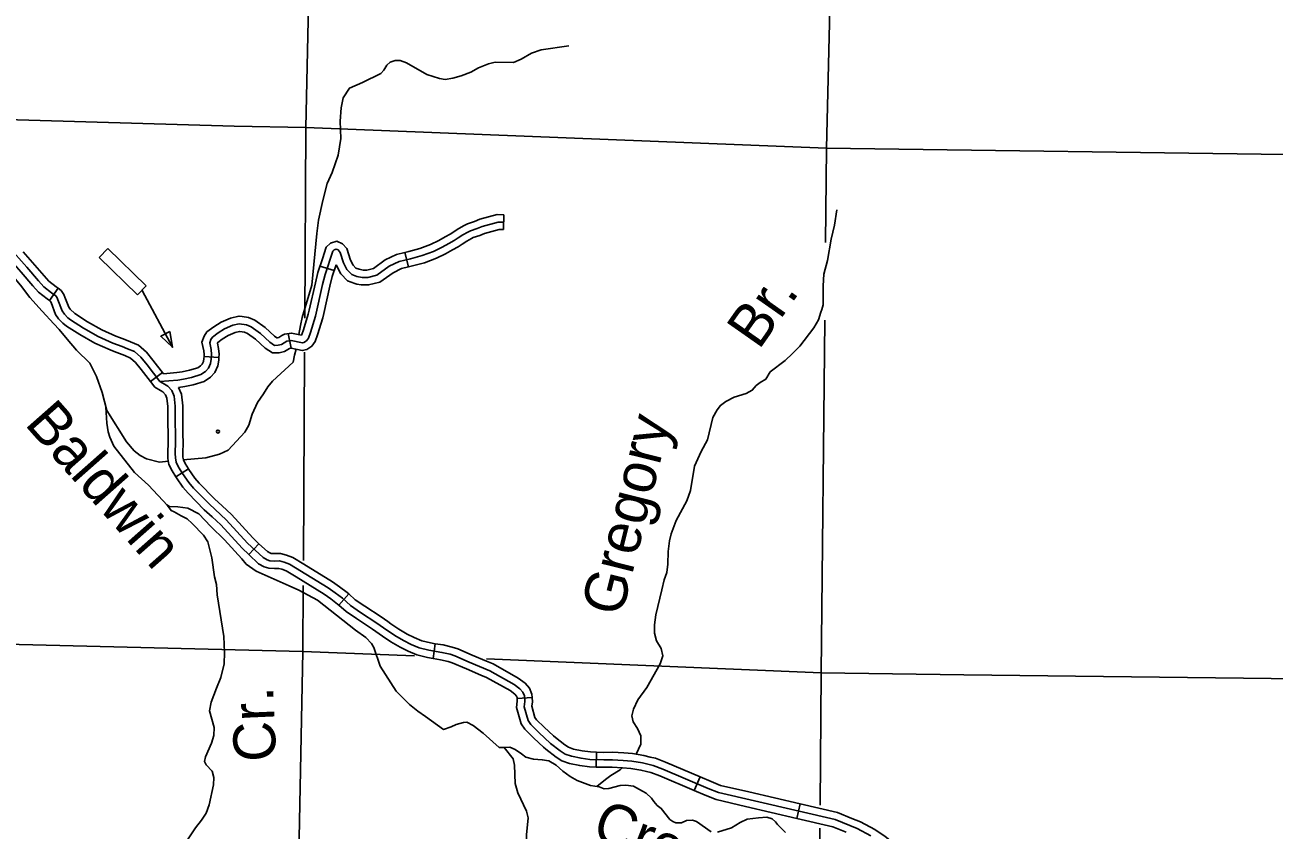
# Model space of a CAD drawing. Extents: x 0 to 3171, y 0 to 2059.
# Drawn here: x 1663.2 to 1872.3, y 380.6 to 515.4 of the extents above; entities that cross this region are included whole.
import ezdxf

# ---------------------------------------------------------------- set-up
doc = ezdxf.new("R2010")
doc.units = 0
for name, color, linetype in [('Level 35', 7, 'Continuous'), ('Level 45', 7, 'Continuous'), ('Level 5', 7, 'Continuous'), ('Level 57', 7, 'Continuous')]:
    doc.layers.add(name, color=color, linetype=linetype)

msp = doc.modelspace()

# ---------------------------------------------------------------- linework, layer by layer
at = {"layer": 'Level 35'}
for points in [[(1754.23, 511.88), (1749.65, 511.2), (1748, 510.68), (1746.26, 509.67), (1744.97, 509.12), (1741.93, 509.17), (1740.82, 508.89), (1739.11, 508.21), (1737.83, 507.46), (1736.21, 506.86), (1734.82, 506.48), (1733.55, 506.25), (1732.6, 506.41), (1730.47, 507.11), (1727.08, 509.02), (1726.03, 509.43), (1725.21, 509.44), (1724.35, 509.16), (1723.78, 508.64), (1723.3, 507.82), (1722.79, 507.24), (1719.74, 505.73), (1717.54, 504.82), (1716.46, 503.16), (1716.13, 501.49), (1715.97, 499.27), (1716.08, 496.34), (1715.63, 493.59), (1714.62, 490.66), (1713.81, 488.85), (1713.07, 485.96), (1712.36, 482.7), (1712.07, 480.48), (1711.26, 471.82)], [(1799.08, 484.44), (1798.69, 481.85), (1798.17, 479.51), (1797.54, 475.95), (1796.92, 473.65), (1796.79, 471.71), (1796.82, 468.5), (1796.62, 467.7), (1796.42, 467.26)], [(1626.29, 482.56), (1629.16, 480.94), (1631.33, 479.93), (1633.71, 479.38), (1637.13, 479.58), (1650.46, 481.71), (1651.54, 481.66), (1654.1, 481.22), (1656.23, 479.5), (1658.01, 477.4), (1659.51, 475.35), (1661.02, 473.52), (1662.47, 471.81), (1664.02, 469.74), (1666.13, 467.43), (1668.06, 465.34)], [(1709.06, 463.54), (1709.32, 465.03), (1709.65, 466.38), (1711.26, 471.82)], [(1796.42, 467.26), (1796.02, 465.99), (1795.27, 464.64), (1792.9, 461.6), (1791.7, 460.36), (1790.44, 459.2), (1787.97, 457.26), (1787.25, 456.06), (1786.29, 455.49), (1785.62, 454.98), (1784.94, 454.2), (1783.92, 453.67), (1781.92, 453.06), (1780.54, 452.32), (1779.61, 451.65), (1779.07, 450.91), (1778.37, 449.63), (1777.45, 445.89), (1776.42, 443.94), (1775.29, 441.5), (1774.64, 437.43), (1773.99, 435.7), (1772.23, 432.38), (1771.38, 430.17), (1771.09, 428.96), (1770.85, 427.21), (1770.8, 425.07), (1770.67, 423.69), (1770.22, 422.46), (1769.8, 420.8), (1768.84, 416.57), (1768.57, 414.93), (1768.57, 413.51), (1768.92, 412.25), (1769.68, 410.95), (1769.97, 409.72), (1769.55, 408.36), (1767.28, 404.42), (1765.8, 402.33), (1765.06, 400.8), (1764.8, 399.66), (1765.02, 398.66), (1765.76, 397.53), (1766.29, 396.35), (1766.31, 394.95), (1765.53, 393.25)], [(1668.06, 465.34), (1668.93, 464.38), (1670.28, 462.75), (1671.84, 460.92), (1674.06, 458.74), (1675.23, 456.48), (1676.13, 453.82), (1676.94, 450.83), (1680.22, 445.56), (1681.52, 444.08), (1682.5, 443.27), (1683.58, 442.69), (1685.75, 442.18), (1687.23, 442.31)], [(1689.73, 442.54), (1693.49, 442.89), (1695.77, 443.48), (1697.24, 444.19), (1700.02, 447.21), (1700.71, 448.36), (1701.25, 450.17), (1702.13, 452.13), (1703.18, 453.6), (1703.9, 454.78), (1704.65, 455.73), (1708.09, 458.93), (1708.34, 460.08), (1708.63, 461.07)], [(1676.79, 451.39), (1676.93, 448.68), (1677.18, 447.22), (1677.41, 446.36), (1678.12, 444.82), (1681.56, 440.42), (1683.93, 438.28), (1687.07, 434.92), (1687.68, 434.08), (1688.19, 433.86), (1689.38, 433.15), (1690.35, 432.67), (1691.21, 431.91), (1693.1, 429.92), (1693.83, 428.83), (1694.5, 426.14), (1694.96, 422.97), (1695.3, 421.67), (1695.39, 419.96), (1696.5, 412.96), (1696.62, 410.31), (1696.56, 408.39), (1696.02, 406.08), (1695.26, 404.3), (1694.41, 401.99), (1694.11, 400.5), (1694.91, 397.75), (1694.85, 396.4), (1694.46, 395.12), (1693.45, 392.79), (1693.28, 392.02), (1693.54, 391.45), (1694.57, 390.39), (1694.86, 389.35), (1694.78, 388.11), (1694.04, 384.78), (1693.53, 383.37), (1692.79, 382.19), (1691.77, 380.91), (1689.45, 377.43)], [(1687, 434.99), (1687.44, 434.73), (1688.83, 434.7), (1690.5, 434.48), (1692.34, 433.53), (1694.34, 431.38), (1696.65, 429.17), (1699.5, 425.99), (1700.27, 425.09), (1701.94, 423.9), (1707.43, 421.45), (1709.04, 420.72), (1712.19, 419.03), (1718.54, 414.04), (1720.29, 412.8), (1721.24, 411.79), (1721.6, 411.12), (1722.7, 408.01), (1725.37, 403.8), (1727.61, 401.59), (1728.96, 400.44), (1730.25, 399.55), (1733.3, 397.4), (1734.54, 397.82), (1735.42, 398.24), (1736.63, 398.56), (1737.18, 398.59), (1738.22, 398.07), (1739.91, 396.76), (1742.6, 394.35), (1743.41, 394.35), (1744.4, 394.42), (1745.25, 394.04), (1746.35, 393.29), (1747.05, 392.73), (1748.33, 392.44), (1749.8, 392.33), (1750.92, 392.12), (1752.13, 391.41), (1753.27, 390.41), (1754.45, 389.5), (1755.66, 388.82), (1757.89, 388), (1759.32, 387.76), (1760.16, 387.46), (1760.94, 387.48), (1762.85, 388.02), (1763.81, 388.07), (1765.07, 387.89), (1766.57, 387.08), (1767.2, 386.7), (1768.07, 385.89), (1768.47, 385.33), (1769.03, 384.66), (1769.71, 384.16), (1771.16, 382.31), (1771.65, 381.97), (1772.16, 381.74), (1773.1, 381.77), (1773.95, 382.17), (1774.96, 382.23), (1775.61, 381.96), (1778.06, 380.27)], [(1743.41, 394.35), (1744.96, 392.49), (1745.18, 391.41), (1745.29, 388.33), (1745.74, 386.76), (1747.18, 383.73), (1747.46, 382.62), (1747.19, 379.75), (1747.22, 378.02), (1747.88, 374.8), (1747.83, 373.13), (1747.53, 369.91), (1746.14, 362.23), (1745.08, 357.51), (1744.8, 355.14), (1744.63, 351.85), (1744.87, 349.04), (1744.26, 345.91), (1744.06, 344.26), (1744.07, 343.11), (1744.12, 342.46)], [(1763.18, 390.97), (1762.82, 390.66), (1761.29, 389.71), (1760.38, 389.04), (1758.93, 387.82)], [(1779.12, 380.21), (1781.48, 380.92), (1782.95, 381.79), (1784.12, 382.37), (1786.02, 382.62), (1787.41, 382.73), (1788.29, 382.42), (1788.85, 381.92), (1789.16, 381.45), (1790.51, 380.11)]]:
    msp.add_lwpolyline(points, dxfattribs=at)
at = {"layer": 'Level 45'}
for p, q in [((1743.37, 483.6), (1743.33, 481.1)), ((1726.8, 477.29), (1727.41, 474.87)), ((1712.6, 475.01), (1714.99, 474.28)), ((1667.33, 469.23), (1668.77, 471.28)), ((1707.28, 463.7), (1707.78, 461.25)), ((1693.2, 459.88), (1695.69, 459.71)), ((1684.26, 455.66), (1686.23, 457.19)), ((1688.47, 439.72), (1690.58, 441.07)), ((1700.69, 426.68), (1702.39, 428.5)), ((1715.77, 418.22), (1717.43, 420.09)), ((1731.53, 409.28), (1731.91, 411.75)), ((1745.6, 402.57), (1748.1, 402.75)), ((1758.8, 391.09), (1758.87, 393.59)), ((1775.25, 387.16), (1776.23, 389.46)), ((1792.4, 382.5), (1792.97, 384.93))]:
    msp.add_line(p, q, dxfattribs=at)
for points in [[(1743.37, 483.6), (1742.27, 483.62), (1739.34, 482.83), (1738.46, 482.46), (1737.3, 482.09), (1736.74, 481.8), (1735.87, 481.29), (1735.06, 480.79), (1734.51, 480.42)], [(1743.35, 482.35), (1742.42, 482.36), (1739.75, 481.64), (1738.9, 481.28), (1737.78, 480.92), (1737.34, 480.7), (1736.52, 480.22), (1735.74, 479.74), (1735.06, 479.29), (1734.19, 478.8), (1733.05, 478.17), (1731.61, 477.45), (1729.69, 476.75), (1727.76, 476.24), (1725.85, 475.76), (1724.18, 474.97), (1722.1, 473.45), (1720.59, 473.08), (1719.67, 473.08), (1718.79, 473.28), (1717.92, 473.59), (1717.11, 474.42), (1716.55, 475.52), (1715.99, 477.29), (1715.63, 477.7), (1715.32, 477.83), (1714.98, 477.74), (1714.74, 477.49), (1713.46, 473.61), (1713.05, 471.89), (1711.85, 466.63), (1711.03, 463.9), (1710.66, 462.94), (1710.34, 462.47), (1709.91, 462.18), (1709.66, 462.13), (1707.81, 462.52), (1707.07, 462.41), (1706.18, 461.88), (1705.6, 461.73), (1705.01, 461.72), (1704.2, 462.26), (1702.64, 463.73), (1701.11, 464.83), (1700.3, 465.15), (1699.09, 465.34), (1698.01, 465.09), (1696.65, 464.48), (1695.55, 463.8), (1694.61, 463.09), (1694.34, 462.68), (1694.15, 462.17), (1694.39, 461.02), (1694.47, 460.21), (1694.42, 459.39), (1694.31, 458.66), (1693.93, 457.9), (1693.44, 457.32), (1692.68, 456.84), (1691.09, 456.33), (1689.75, 456.07), (1688.79, 455.91), (1685.83, 455.67)], [(1743.33, 481.1), (1742.58, 481.11), (1740.16, 480.46), (1739.33, 480.11), (1738.25, 479.76), (1737.94, 479.61), (1737.16, 479.15), (1736.41, 478.69), (1735.9, 478.34)], [(1719.36, 474.43), (1719.15, 474.48), (1718.61, 474.67), (1718.14, 475.16), (1717.71, 476), (1717.1, 477.92), (1716.38, 478.73), (1715.41, 479.15), (1714.34, 478.86), (1713.64, 478.17), (1713, 476.22)], [(1734.51, 480.42), (1734.41, 480.35), (1733.58, 479.89), (1732.47, 479.28), (1731.11, 478.6), (1729.32, 477.94), (1727.45, 477.45), (1726.8, 477.29)], [(1660.47, 478.29), (1663.55, 474.81), (1665.48, 472.52), (1666.37, 471.53), (1667.7, 470.5), (1668.4, 470.01), (1668.63, 469.67), (1668.76, 469.35), (1669.45, 467.48), (1669.84, 466.97), (1670.41, 466.34), (1670.88, 465.98)], [(1662.92, 477.41), (1664.5, 475.62), (1666.42, 473.34), (1667.23, 472.45), (1668.44, 471.5), (1668.77, 471.28)], [(1726.8, 477.29), (1725.42, 476.95), (1723.54, 476.05), (1721.56, 474.61), (1720.43, 474.33), (1719.81, 474.33), (1719.36, 474.43)], [(1735.9, 478.34), (1735.72, 478.22), (1734.79, 477.7), (1733.63, 477.07), (1732.1, 476.3), (1730.07, 475.55), (1728.07, 475.03), (1727.41, 474.87)], [(1661.05, 475.75), (1662.61, 473.99), (1664.54, 471.7), (1665.52, 470.61), (1666.96, 469.49), (1667.33, 469.23)], [(1713, 476.22), (1712.25, 473.95), (1711.84, 472.17), (1710.79, 467.59)], [(1715.3, 475.22), (1714.66, 473.28), (1714.27, 471.61), (1713.23, 467.03)], [(1718.8, 471.99), (1718.44, 472.08), (1717.22, 472.51), (1716.08, 473.68), (1715.3, 475.22)], [(1727.41, 474.87), (1726.27, 474.58), (1724.83, 473.89), (1722.64, 472.3), (1720.74, 471.83), (1719.52, 471.83), (1718.8, 471.99)], [(1668.77, 471.28), (1669.31, 470.9), (1669.74, 470.26), (1669.93, 469.81), (1670.56, 468.09), (1670.8, 467.77), (1671.55, 467.03)], [(1667.33, 469.23), (1667.5, 469.11), (1667.53, 469.07), (1667.6, 468.9), (1668.34, 466.88), (1668.87, 466.17), (1669.56, 465.42), (1670.2, 464.92)], [(1671.55, 467.03), (1673.69, 465.67), (1676.08, 464.3), (1678.43, 463.27), (1679.07, 463.02)], [(1699.57, 466.53), (1699.04, 466.62), (1697.61, 466.28), (1696.06, 465.59), (1694.84, 464.83), (1693.69, 463.97), (1693.21, 463.25), (1692.85, 462.26), (1693.15, 460.83), (1693.22, 460.19), (1693.2, 459.88)], [(1706.22, 463.36), (1705.7, 463.04), (1705.44, 462.98), (1705.37, 462.98), (1704.98, 463.24), (1703.44, 464.69), (1701.71, 465.94), (1700.64, 466.36), (1699.57, 466.53)], [(1710.79, 467.59), (1710.64, 466.95), (1709.84, 464.3), (1709.55, 463.52), (1709.49, 463.44), (1707.85, 463.79), (1706.64, 463.61), (1706.22, 463.36)], [(1713.23, 467.03), (1713.06, 466.31), (1712.21, 463.5), (1711.78, 462.36), (1711.24, 461.57), (1710.4, 461), (1709.64, 460.86), (1707.78, 461.25), (1707.5, 461.21), (1707.51, 461.22)], [(1670.2, 464.92), (1672.4, 463.53), (1674.95, 462.07), (1677.48, 460.95), (1678.17, 460.68)], [(1670.88, 465.98), (1673.04, 464.6), (1675.51, 463.18), (1677.95, 462.11), (1679.5, 461.51), (1680.4, 461.16), (1681.54, 460.67), (1682.65, 459.72), (1683.66, 458.47), (1685.83, 455.67), (1686.57, 455.24), (1687.14, 454.88), (1687.79, 454.15), (1688.22, 453.22), (1688.39, 451.54), (1688.38, 448.93), (1688.43, 446.77), (1688.43, 445.54), (1688.39, 443.59), (1688.4, 442.87), (1688.53, 442.14), (1688.94, 441.3), (1689.62, 440.24), (1690.68, 438.74), (1691.45, 437.79), (1694.11, 435.1), (1696.92, 432.52), (1700.45, 428.6), (1703.07, 426.17), (1703.76, 425.78), (1704.24, 425.65), (1705, 425.6), (1705.85, 425.63), (1706.61, 425.43), (1707.51, 425.07), (1714, 421.1), (1715.14, 420.27), (1716.35, 419.37), (1717.74, 418.14), (1719.4, 417), (1722.11, 415.22), (1723.24, 414.42), (1725.15, 413.14), (1726.61, 412.29), (1727.86, 411.64), (1729.23, 411.08), (1730.85, 410.65), (1733.01, 410.31), (1734.39, 410), (1735.2, 409.71), (1737.6, 408.68), (1741.02, 407.24), (1745.1, 404.95), (1746.08, 404.21), (1746.58, 403.65), (1746.82, 403.05), (1746.89, 402.08), (1746.76, 401.19), (1747.44, 398.88), (1747.87, 398.23), (1749.23, 396.86), (1751.19, 395.07), (1752.83, 393.79), (1753.63, 393.28), (1754.71, 392.9), (1756.29, 392.57), (1757.79, 392.37), (1760.12, 392.31), (1761.54, 392.33), (1763.35, 392.22), (1764.79, 392.1), (1766.58, 391.81), (1768.37, 391.36), (1769.96, 390.76), (1777.57, 387.53), (1779.28, 386.83), (1798.82, 382.29), (1802.53, 380.79), (1804.79, 379.57)], [(1699.18, 464.06), (1699.14, 464.07), (1698.41, 463.9), (1697.24, 463.38), (1696.26, 462.76), (1695.53, 462.22), (1695.46, 462.11), (1695.45, 462.08), (1695.63, 461.21), (1695.73, 460.23), (1695.69, 459.71)], [(1707.51, 461.22), (1706.67, 460.71), (1705.77, 460.48), (1704.64, 460.46), (1703.42, 461.27), (1701.84, 462.76), (1700.5, 463.73), (1699.97, 463.94), (1699.18, 464.06)], [(1679.07, 463.02), (1679.96, 462.68), (1680.87, 462.31), (1682.21, 461.74), (1683.56, 460.59), (1684.64, 459.25), (1686.41, 456.97)], [(1678.17, 460.68), (1679.05, 460.35), (1679.92, 460), (1680.87, 459.59), (1681.75, 458.84), (1682.68, 457.7), (1684.26, 455.66)], [(1693.2, 459.88), (1693.17, 459.52), (1693.1, 459.04), (1692.88, 458.59), (1692.61, 458.28), (1692.14, 457.98), (1690.79, 457.54), (1689.52, 457.3), (1688.64, 457.15), (1687.55, 457.06)], [(1695.69, 459.71), (1695.66, 459.26), (1695.52, 458.28), (1694.98, 457.2), (1694.27, 456.37), (1693.22, 455.69), (1691.4, 455.12), (1689.97, 454.84), (1688.93, 454.67)], [(1687.55, 457.06), (1686.41, 456.97)], [(1684.26, 455.66), (1684.99, 454.72), (1685.92, 454.17), (1686.32, 453.92), (1686.73, 453.45), (1687, 452.89), (1687.14, 451.48), (1687.13, 448.92), (1687.14, 448.89)], [(1688.93, 454.67), (1689.45, 453.56), (1689.64, 451.6), (1689.63, 448.95), (1689.63, 448.94)], [(1687.14, 448.89), (1687.18, 446.75), (1687.18, 445.55), (1687.14, 443.59), (1687.16, 442.75), (1687.33, 441.75), (1687.85, 440.69), (1688.47, 439.72)], [(1689.63, 448.94), (1689.68, 446.78), (1689.69, 445.53), (1689.64, 443.59), (1689.65, 443), (1689.74, 442.53), (1690.04, 441.91), (1690.58, 441.07)], [(1688.47, 439.72), (1688.59, 439.54), (1689.68, 437.99), (1690.52, 436.95), (1693.24, 434.2), (1694.57, 432.98)], [(1690.58, 441.07), (1690.66, 440.94), (1691.68, 439.5), (1692.39, 438.62), (1694.97, 436), (1696.26, 434.82)], [(1696.26, 434.82), (1697.81, 433.4), (1701.34, 429.48), (1702.39, 428.5)], [(1694.57, 432.98), (1696.03, 431.64), (1699.56, 427.73), (1700.69, 426.68)], [(1700.69, 426.68), (1702.33, 425.14), (1703.29, 424.62), (1704.02, 424.41), (1704.98, 424.35), (1705.7, 424.37), (1706.22, 424.24), (1706.95, 423.95), (1708.61, 422.93)], [(1702.39, 428.5), (1703.81, 427.19), (1704.24, 426.95), (1704.45, 426.89), (1705.02, 426.86), (1706, 426.88), (1707, 426.61), (1708.07, 426.19), (1709.92, 425.06)], [(1709.92, 425.06), (1714.69, 422.14), (1715.88, 421.28), (1717.14, 420.34), (1717.43, 420.09)], [(1708.61, 422.93), (1713.3, 420.06), (1714.4, 419.26), (1715.56, 418.4), (1715.77, 418.22)], [(1715.77, 418.22), (1716.97, 417.15), (1718.7, 415.96), (1721.41, 414.19), (1722.53, 413.39), (1723.07, 413.03)], [(1717.43, 420.09), (1718.51, 419.13), (1720.1, 418.03), (1722.82, 416.26), (1723.96, 415.45), (1724.46, 415.1)], [(1724.46, 415.1), (1725.81, 414.2), (1727.21, 413.38), (1728.39, 412.77), (1729.63, 412.26), (1731.11, 411.88), (1731.91, 411.75)], [(1723.07, 413.03), (1724.48, 412.08), (1726, 411.19), (1727.34, 410.5), (1728.83, 409.89), (1730.6, 409.42), (1731.53, 409.28)], [(1731.91, 411.75), (1733.24, 411.54), (1734.75, 411.2), (1735.66, 410.87), (1738.09, 409.83), (1740.49, 408.82)], [(1731.53, 409.28), (1732.77, 409.08), (1734.04, 408.8), (1734.74, 408.54), (1737.11, 407.53), (1739.52, 406.51)], [(1740.49, 408.82), (1741.57, 408.36), (1745.78, 406), (1746.94, 405.14), (1747.65, 404.32), (1748.06, 403.33), (1748.1, 402.75)], [(1739.52, 406.51), (1740.47, 406.11), (1744.41, 403.9), (1745.23, 403.29), (1745.5, 402.99), (1745.59, 402.76), (1745.6, 402.57)], [(1745.6, 402.57), (1745.63, 402.13), (1745.49, 401.09), (1746.3, 398.35), (1746.89, 397.44), (1748.37, 395.95), (1750.02, 394.45)], [(1748.1, 402.75), (1748.15, 402.04), (1748.04, 401.28), (1748.59, 399.41), (1748.85, 399.02), (1750.1, 397.76), (1751.7, 396.3)], [(1751.7, 396.3), (1752, 396.02), (1753.56, 394.81), (1754.18, 394.41), (1755.04, 394.11), (1756.5, 393.81), (1757.89, 393.62), (1758.87, 393.59)], [(1750.02, 394.45), (1750.39, 394.11), (1752.11, 392.77), (1753.08, 392.14), (1754.38, 391.7), (1756.08, 391.34), (1757.69, 391.13), (1758.8, 391.09)], [(1758.87, 393.59), (1760.13, 393.56), (1761.56, 393.58), (1763.44, 393.46), (1764.93, 393.35), (1766.83, 393.04), (1767.88, 392.78)], [(1758.8, 391.09), (1760.12, 391.06), (1761.51, 391.08), (1763.26, 390.97), (1764.64, 390.86), (1766.33, 390.59), (1767.27, 390.35)], [(1767.88, 392.78), (1768.75, 392.56), (1770.43, 391.92), (1776.23, 389.46)], [(1767.27, 390.35), (1768, 390.17), (1769.5, 389.6), (1775.25, 387.16)], [(1776.23, 389.46), (1778.05, 388.68), (1779.66, 388.03), (1784.4, 386.93)], [(1775.25, 387.16), (1777.09, 386.37), (1778.9, 385.64), (1783.83, 384.49)], [(1784.4, 386.93), (1792.97, 384.93)], [(1792.97, 384.93), (1799.2, 383.49), (1801.61, 382.51)], [(1783.83, 384.49), (1792.4, 382.5)], [(1792.4, 382.5), (1798.45, 381.1), (1800.67, 380.19)], [(1801.61, 382.51), (1803.07, 381.92), (1805.44, 380.63), (1807.17, 379.45), (1809.36, 377.72)]]:
    msp.add_lwpolyline(points, dxfattribs=at)
at = {"layer": 'Level 5'}
for points in [[(1712.21, 587.86), (1710.23, 498.22)], [(1797.38, 494.75), (1799.55, 585.69)], [(1623.7, 500.62), (1698.24, 498.43), (1710.23, 498.22)], [(1710.23, 498.22), (1710.05, 466.28)], [(1710.23, 498.22), (1797.38, 494.75)], [(1797.22, 478.97), (1797.38, 494.75)], [(1797.38, 494.75), (1878.23, 493.63)], [(1796.48, 406.89), (1797.08, 465.92)], [(1710.02, 460.56), (1709.83, 425.67)], [(1709.81, 421.53), (1709.75, 410.47)], [(1709.75, 410.47), (1621.55, 412.63)], [(1709.75, 410.47), (1708.01, 322.32)], [(1728.44, 409.7), (1709.75, 410.47)], [(1796.48, 406.89), (1740.48, 409.2)], [(1796.48, 406.89), (1796.29, 384.74)], [(1885.85, 405.77), (1820.35, 406.53), (1796.48, 406.89)], [(1796.26, 380.86), (1795.72, 317.71)]]:
    msp.add_lwpolyline(points, dxfattribs=at)
at = {"layer": 'Level 57'}
for p, q in [((1677.12, 477.92), (1675.67, 476.43)), ((1683.54, 471.68), (1677.12, 477.92)), ((1675.67, 476.43), (1682.09, 470.18)), ((1682.09, 470.18), (1683.54, 471.68))]:
    msp.add_line(p, q, dxfattribs=at)
msp.add_lwpolyline([(1682.82, 470.93), (1687.93, 461.4)], dxfattribs=at)
msp.add_lwpolyline([(1687.47, 464.05), (1685.97, 463.24), (1687.93, 461.4)], close=True, dxfattribs=at)
msp.add_circle((1695.53, 447.29), 0.25, dxfattribs=at)

# ---------------------------------------------------------------- texts
at = {"layer": 'Level 35'}
for s, rotation, p in [('Br.', 54.9427, (1786.05, 460.82)), ('Baldwin', 311.4563, (1663.02, 448.52)), ('Gregory', 75.9627, (1763.06, 416.1)), ('Cr.', 92.5068, (1705.3, 392.13)), ('Creek', 338.8972, (1757.81, 379.25))]:
    msp.add_text(s, height=7.04, rotation=rotation, dxfattribs=at).set_placement(p)

doc.saveas('drawing.dxf')
